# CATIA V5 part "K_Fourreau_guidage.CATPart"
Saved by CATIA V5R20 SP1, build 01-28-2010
Part number: fourreau_guidage
Bounding box of the stored display mesh (mm): x -9.997 to 9.997, y -9.997 to 9.997, z -20 to 10
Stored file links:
  G:\Khaled_CFAO_2011\SIL\SIL_GR1\mroland\Khaled\CAD_CATIA_Modifie\K_Fourreau_guidage.CATPart
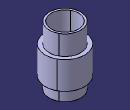
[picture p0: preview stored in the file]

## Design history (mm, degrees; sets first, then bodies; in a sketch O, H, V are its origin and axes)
Set1
  Sketch1 on zx-plane, origin (0, 0, 0), H (-1, 0, 0), V (0, 0, 1)
    line L1 (7, 10) -> (7, -20)
    line L2 (7, -20) -> (8, -20)
    line L3 (8, -20) -> (8, -14)
    line L4 (8, -14) -> (10, -14)
    line L5 (10, -14) -> (10, 0)
    point P6 (10, 0)
    line L6 (10, 0) -> (8, 0)
    point P7 (8, 0)
    line L7 (8, 0) -> (8, 10)
    line L8 (8, 10) -> (7, 10)
    length L8 = 1
    length L6 = 2
    length L7 = 10
    length L3 = 6
    length L1 = 30
    distance V L1 = 7
    vertical: L1 V, L3 V, L5 V, L7 V
    horizontal: L2 H, L4 H, L6 H, L8 H
    coincidence: P6 H, P7 L3
Body1 (main body)
  Shaft1: profile Sketch1, axis Sketch1.V, angle 360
